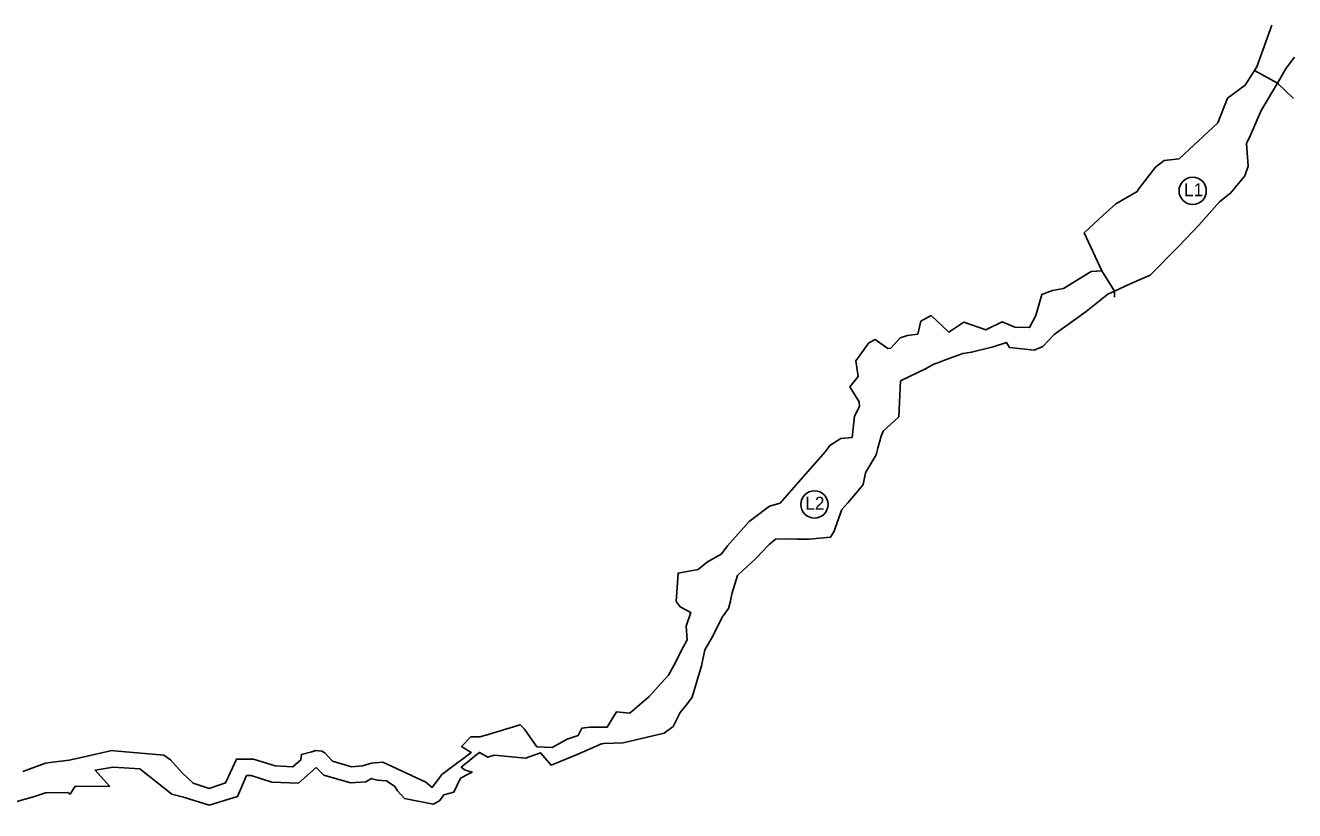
# Model space of a CAD drawing. Extents: x -445081 to -429827, y -1135509 to -1130100.
# Drawn here: x -441644 to -440454, y -1132107 to -1131370 of the extents above; entities that cross this region are included whole.
import ezdxf

# ---------------------------------------------------------------- set-up
doc = ezdxf.new("R2010")
doc.units = 0
for name, color, linetype in [('Vrstva 32', 7, 'Continuous'), ('Vrstva 33', 7, 'Continuous'), ('Vrstva 36', 7, 'Continuous')]:
    doc.layers.add(name, color=color, linetype=linetype)

msp = doc.modelspace()

# ---------------------------------------------------------------- linework, layer by layer
at = {"layer": 'Vrstva 32'}
for points in [[(-440622.6, -1131619.6), (-440608.4, -1131613.2), (-440598.5, -1131608.8), (-440589.9, -1131605), (-440589, -1131604.6), (-440562.6, -1131577.8), (-440549.1, -1131563.6), (-440543.4, -1131557.6), (-440524.2, -1131535.8), (-440514.7, -1131528.5), (-440513.8, -1131527.8), (-440500.5, -1131511.6), (-440497.2, -1131502.5), (-440498.7, -1131481.2), (-440495.2, -1131473.3), (-440485, -1131450.2), (-440469.9, -1131424.5), (-440491.3, -1131412.9), (-440500, -1131426.5), (-440516.8, -1131438.7), (-440525.6, -1131461.9), (-440561.9, -1131495.4), (-440575.9, -1131497), (-440584.1, -1131503.4), (-440600.2, -1131524.1), (-440601.3, -1131526.1), (-440621.3, -1131537.7), (-440633.1, -1131548.5), (-440651, -1131564.8), (-440634.6, -1131600.4), (-440622.6, -1131619.6)], [(-440454.8, -1131439), (-440469.9, -1131424.5), (-440491.3, -1131412.9), (-440500, -1131426.5), (-440516.8, -1131438.7), (-440525.6, -1131461.9), (-440561.9, -1131495.4), (-440575.9, -1131497), (-440584.1, -1131503.4), (-440600.2, -1131524.1), (-440601.3, -1131526.1), (-440621.3, -1131537.7), (-440633.1, -1131548.5), (-440651, -1131564.8), (-440634.6, -1131600.4), (-440622.6, -1131619.6), (-440622.6, -1131625.1)]]:
    msp.add_lwpolyline(points, dxfattribs=at)
at = {"layer": 'Vrstva 33'}
for points in [[(-440491.3, -1131412.9), (-440489.2, -1131409.3), (-440475, -1131370.4)], [(-440453.7, -1131400.1), (-440461.6, -1131410.5), (-440469.9, -1131424.5)], [(-441645.9, -1132069.8), (-441624.7, -1132062.1), (-441620.2, -1132061.5), (-441602.6, -1132059.4), (-441589.8, -1132056.5), (-441562.4, -1132050.3), (-441560.4, -1132050.4), (-441513.7, -1132054.6), (-441507.6, -1132058.9), (-441496.7, -1132071.2), (-441486.3, -1132080.7), (-441471.2, -1132085.8), (-441461.4, -1132082.4), (-441455.9, -1132080.5), (-441453.1, -1132074.5), (-441445.7, -1132058.3), (-441429.7, -1132058.4), (-441409.4, -1132064.7), (-441392.8, -1132065.4), (-441385.4, -1132059), (-441385.4, -1132058.8), (-441384.8, -1132053.9), (-441375, -1132051.4), (-441371.2, -1132050.3), (-441365.7, -1132050.8), (-441363, -1132052.5), (-441355.6, -1132060.1), (-441337.9, -1132065.5), (-441327.4, -1132064.7), (-441319, -1132062.2), (-441308.6, -1132061.2), (-441268.3, -1132079.8), (-441262.2, -1132084.8), (-441253.2, -1132072.8), (-441239.3, -1132062.3), (-441232.7, -1132057.4), (-441225.6, -1132052.1), (-441234.6, -1132046.5), (-441226, -1132037.4), (-441217.5, -1132037.5), (-441211.9, -1132035.8), (-441179.8, -1132026.1), (-441175.8, -1132030.1), (-441164, -1132046.9), (-441149.7, -1132047.5), (-441135.6, -1132039.6), (-441125.3, -1132036.3), (-441121.8, -1132029.2), (-441114.3, -1132028.3), (-441098.1, -1132028.3), (-441093.4, -1132020.4), (-441089.4, -1132013.9), (-441076.9, -1132015.2), (-441058.8, -1131999.5), (-441047.3, -1131986.9), (-441040.6, -1131979.5), (-441035.7, -1131970.4), (-441027.1, -1131954), (-441023.1, -1131946.6), (-441024.2, -1131933.8), (-441019.8, -1131920.8), (-441029.8, -1131915.5), (-441033.5, -1131910.5), (-441031.7, -1131883.9), (-441012.9, -1131880.4), (-441012.5, -1131880.3), (-441004, -1131873.5), (-440990.7, -1131865.8), (-440990.6, -1131865.6), (-440985.5, -1131858.2), (-440965.2, -1131835.4), (-440946.1, -1131821.1), (-440936.1, -1131818.5), (-440916.7, -1131796.3), (-440893.5, -1131769.8), (-440889.3, -1131764.4), (-440879.1, -1131757.8), (-440868.5, -1131756.7), (-440866.3, -1131736.9), (-440861.5, -1131727.7), (-440861.8, -1131723.2), (-440870.7, -1131709.2), (-440862.8, -1131699.5), (-440865, -1131684.9), (-440852.8, -1131668.2), (-440846.8, -1131665), (-440835.2, -1131673.4), (-440832.2, -1131673.2), (-440823.5, -1131663.5), (-440816.7, -1131661.1), (-440806.8, -1131659.9), (-440804, -1131647.6), (-440794.3, -1131642.5), (-440777.8, -1131658.2), (-440763.8, -1131648.6), (-440743.1, -1131655.9), (-440727.9, -1131648.3), (-440716.1, -1131653.5), (-440702.2, -1131653.8), (-440696.4, -1131642.3), (-440690.7, -1131622.6), (-440680.7, -1131619), (-440670.4, -1131617.2), (-440644.4, -1131601.1), (-440634.6, -1131600.4)], [(-440622.6, -1131619.6), (-440628.8, -1131622.3), (-440649, -1131638.6), (-440679.3, -1131660.1), (-440689.7, -1131671.4), (-440698, -1131674.9), (-440721.1, -1131672.4), (-440723.8, -1131667.7), (-440736.4, -1131671.8), (-440738.9, -1131672.4), (-440755.4, -1131676.6), (-440756.6, -1131676.9), (-440764.7, -1131677.9), (-440782, -1131684.4), (-440788.3, -1131686.7), (-440791.8, -1131688), (-440800.5, -1131692.6), (-440806.8, -1131696), (-440823.2, -1131703.7), (-440824.8, -1131737.5), (-440839.3, -1131751), (-440841.2, -1131755.6), (-440844.3, -1131766.8), (-440846, -1131773.1), (-440854.8, -1131787.8), (-440856, -1131789.8), (-440858.1, -1131801), (-440863.5, -1131807.3), (-440872.7, -1131818), (-440878.2, -1131824.4), (-440884, -1131840.7), (-440885.4, -1131844.5), (-440888.9, -1131850.3), (-440908.9, -1131852.2), (-440920.2, -1131852.2), (-440930.5, -1131851.9), (-440940.4, -1131852), (-440946.3, -1131857.1), (-440948, -1131858.8), (-440952.1, -1131863), (-440959.6, -1131870.7), (-440971, -1131881.6), (-440975.7, -1131886), (-440975.9, -1131886.1), (-440980.9, -1131902.3), (-440982.2, -1131907.9), (-440982.7, -1131910.1), (-440984.3, -1131917.1), (-440990.5, -1131925.2), (-440999.2, -1131943.1), (-441006.5, -1131955.8), (-441009.7, -1131971), (-441018.5, -1132000.1), (-441023.7, -1132007.3), (-441029.6, -1132014.7), (-441033.8, -1132022.8), (-441036.3, -1132027.7), (-441044.8, -1132033.9), (-441083.1, -1132042.9), (-441101.3, -1132043.8), (-441103.5, -1132043.9), (-441126.3, -1132054), (-441142.4, -1132060.6), (-441150.7, -1132064.1), (-441160.6, -1132052.4), (-441174.9, -1132057.4), (-441204.1, -1132054.6), (-441210, -1132056.6), (-441217.9, -1132052), (-441221.3, -1132054.7), (-441228.7, -1132060.7), (-441235, -1132065.8), (-441231.2, -1132068.7), (-441224.9, -1132070.6), (-441228, -1132072.1), (-441235.8, -1132076.2), (-441241.8, -1132089.2), (-441251.3, -1132091.8), (-441255.5, -1132097.3), (-441261.4, -1132100.6), (-441288.3, -1132095.2), (-441294.8, -1132087.9), (-441297.2, -1132083.9), (-441305.1, -1132078.7), (-441305.4, -1132078.7), (-441313.6, -1132078.1), (-441314.8, -1132077.8), (-441318.6, -1132076.7), (-441319.2, -1132076.5), (-441324.3, -1132079.7), (-441338.8, -1132080.6), (-441363.8, -1132073.4), (-441370.9, -1132066.2), (-441387.6, -1132080.9), (-441412.7, -1132079.8), (-441431.9, -1132073.7), (-441436.2, -1132073.7), (-441444.7, -1132093.2), (-441471.3, -1132101.5), (-441495.2, -1132094), (-441506.3, -1132091.2), (-441536.4, -1132067.5), (-441561.2, -1132065.7), (-441578.2, -1132068.7), (-441564.7, -1132083.6), (-441595.3, -1132084.1), (-441596.9, -1132083.8), (-441601.5, -1132091.1), (-441603, -1132090.2), (-441603.7, -1132089.7), (-441624.7, -1132089.8), (-441634.2, -1132092.9), (-441681.1, -1132106.6)]]:
    msp.add_lwpolyline(points, dxfattribs=at)
at = {"layer": 'Vrstva 36'}
for centre in [(-440549.3, -1131525.6), (-440903.9, -1131819.5)]:
    msp.add_circle(centre, 12.8, dxfattribs=at)

# ---------------------------------------------------------------- texts
for s, p in [('L1', (-440557.4, -1131530.6)), ('L2', (-440912.4, -1131824.4))]:
    msp.add_text(s, height=12, dxfattribs=at).set_placement(p)

doc.saveas('drawing.dxf')
